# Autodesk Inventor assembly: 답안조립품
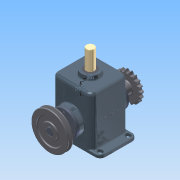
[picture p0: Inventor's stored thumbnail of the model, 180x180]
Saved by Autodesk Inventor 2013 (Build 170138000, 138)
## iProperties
Created: 2015-03
Part Number: 답안조립품
Document SubType Name: Assembly
Designer: Administrator
Author: Administrator
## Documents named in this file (15)
- C:\Documents and Settings\Administrator\바탕 화면\350305V1014\답안조립품.iam
- C:\Documents and Settings\Administrator\바탕 화면\350305V1014\본체.ipt
- C:\Documents and Settings\Administrator\바탕 화면\350305V1014\7가변스프링.ipt
- C:\Documents and Settings\Administrator\바탕 화면\350305V1014\멈춤나사 M5x0.5.ipt
- C:\Documents and Settings\Administrator\바탕 화면\350305V1014\멈춤링.ipt
- C:\Documents and Settings\Administrator\바탕 화면\350305V1014\베어링 6205.ipt
- C:\Documents and Settings\Administrator\바탕 화면\350305V1014\부시.ipt
- C:\Documents and Settings\Administrator\바탕 화면\350305V1014\슬라이드.ipt
- C:\Documents and Settings\Administrator\바탕 화면\350305V1014\오일실.ipt
- C:\Documents and Settings\Administrator\바탕 화면\350305V1014\체인 스프로킷.ipt
- C:\Documents and Settings\Administrator\바탕 화면\350305V1014\커버.ipt
- C:\Documents and Settings\Administrator\바탕 화면\350305V1014\키 8x8.ipt
- C:\Documents and Settings\Administrator\바탕 화면\350305V1014\편심축.ipt
- C:\Documents and Settings\Administrator\바탕 화면\350305V1014\M4x0.5.ipt
- C:\Documents and Settings\Administrator\바탕 화면\350305V1014\V-벨트풀리.ipt
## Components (9 placed, 4 different names)
1. 7가변스프링:1
2. 5-체인 스프로킷:1 — 플러쉬:4, 각도:4
3. V-벨트풀리:1 — 플러쉬:3, 각도:3
4. M4x0.5:2
5. M4x0.5:1
6. M4x0.5:3
7. M4x0.5:4
8. M4x0.5:5
9. M4x0.5:6
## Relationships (4: Flush 2, Angle 2)
- 플러쉬:3 [Flush]: V-벨트풀리:1
- 플러쉬:4 [Flush]: 5-체인 스프로킷:1
- 각도:3 [Angle]: V-벨트풀리:1
- 각도:4 [Angle]: 5-체인 스프로킷:1
